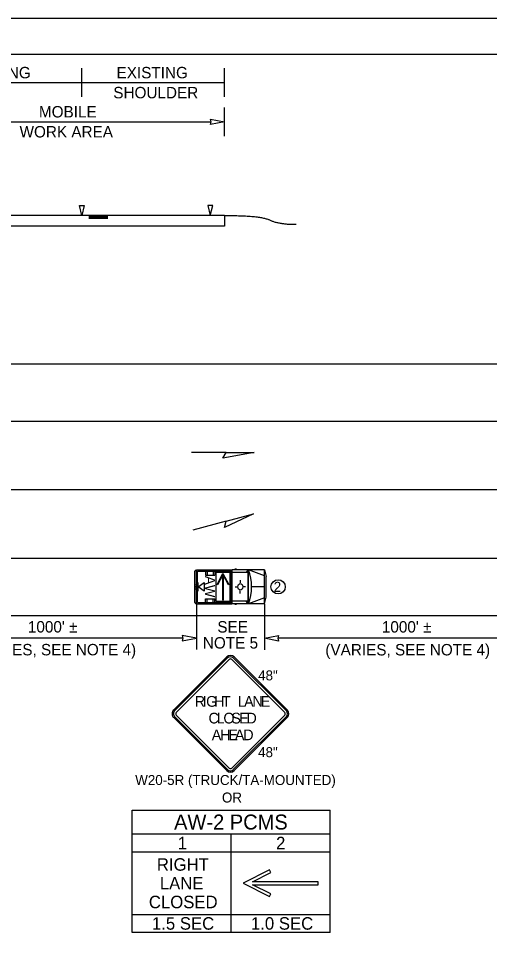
# Model space of a CAD drawing. Extents: x 0 to 17, y 0 to 11.
# Drawn here: x 8.41 to 11.71, y 4.59 to 11 of the extents above; entities that cross this region are included whole.
import ezdxf

# ---------------------------------------------------------------- set-up
doc = ezdxf.new("R2010")
doc.units = 0
for name, color, linetype in [('RD_ED_ShoulderPavedEdge', 7, 'Continuous'), ('RD_MK_LineEdgeWhite', 7, 'Continuous'), ('RD_MK_LineEdgeYellow', 7, 'Continuous'), ('RD_MK_LineLane', 7, 'Continuous'), ('SH_GI_PlotLimits', 7, 'Continuous'), ('SH_GI_SheetBorder3', 7, 'Continuous'), ('SH_TI_WZSectionCut', 7, 'Continuous'), ('TR_SN_ConstructionSigns', 7, 'Continuous'), ('TR_WZ_PortableChangeMessageSign', 7, 'Continuous'), ('TR_WZ_PortableSignMountBlk-Org', 7, 'Continuous'), ('TR_WZ_ProtectiveVehicle', 7, 'Continuous'), ('TR_WZ_TransportableAttenuator', 7, 'Continuous'), ('TR_WZ_WorkZoneDetails', 7, 'Continuous'), ('TR_WZ_WorkZoneTextCurrent', 7, 'Continuous')]:
    doc.layers.add(name, color=color, linetype=linetype)

msp = doc.modelspace()

# ---------------------------------------------------------------- linework, layer by layer
at = {"layer": 'RD_ED_ShoulderPavedEdge'}
for p, q in [((1.8283, 8.5807), (16.62, 8.5807)), ((1.8283, 6.8207), (16.62, 6.8207))]:
    msp.add_line(p, q, dxfattribs=at)
at = {"layer": 'RD_MK_LineEdgeWhite'}
msp.add_line((1.8283, 7.2207), (16.62, 7.2207), dxfattribs=at)
at = {"layer": 'RD_MK_LineEdgeYellow'}
msp.add_line((1.8283, 8.1807), (16.62, 8.1807), dxfattribs=at)
at = {"layer": 'RD_MK_LineLane'}
msp.add_line((16.62, 7.7007), (1.8283, 7.7007), dxfattribs=at)
at = {"layer": 'SH_GI_PlotLimits'}
msp.add_lwpolyline([(0, 11), (17, 11), (17, 0), (0, 0)], close=True, dxfattribs=at)
at = {"layer": 'SH_GI_SheetBorder3'}
msp.add_line((1, 10.75), (16.75, 10.75), dxfattribs=at)
at = {"layer": 'SH_TI_WZSectionCut'}
for p, q in [((8.8546, 10.45), (8.8546, 10.65)), ((9.8546, 10.45), (9.8546, 10.65)), ((7.6546, 10.55), (8.8546, 10.55)), ((8.8546, 10.55), (9.8546, 10.55)), ((9.8546, 10.176), (9.8546, 10.376)), ((7.7484, 10.276), (9.7609, 10.276)), ((9.8546, 9.6199), (5.4546, 9.6199)), ((9.0376, 9.6143), (8.9046, 9.6143)), ((9.0376, 9.6087), (8.9046, 9.6087)), ((9.0376, 9.603), (8.9046, 9.603)), ((9.0376, 9.5978), (8.9046, 9.5978)), ((9.8546, 9.6199), (9.8546, 9.5449)), ((9.8546, 9.5449), (5.4546, 9.5449))]:
    msp.add_line(p, q, dxfattribs=at)
for points in [[(9.8546, 10.276), (9.7564, 10.2567), (9.7609, 10.276), (9.7564, 10.2953)], [(8.838, 9.6897), (8.8713, 9.6897), (8.8547, 9.6199)]]:
    msp.add_lwpolyline(points, close=True, dxfattribs=at)
msp.add_lwpolyline([(9.7713, 9.6897), (9.7379, 9.6897), (9.7546, 9.6199), (9.7713, 9.6897)], dxfattribs=at)
msp.add_open_spline([(9.8546, 9.6199), (10.1058, 9.6201), (10.2313, 9.558), (10.3568, 9.5581)], degree=2, dxfattribs=at)
at = {"layer": 'TR_SN_ConstructionSigns'}
for p, q in [((9.8694, 6.5301), (9.4982, 6.1588)), ((9.876, 6.5234), (9.5048, 6.1522)), ((9.5158, 6.1411), (9.8871, 6.5124)), ((9.9048, 6.5124), (10.276, 6.1411)), ((10.2871, 6.1522), (9.9158, 6.5234)), ((10.2937, 6.1588), (9.9224, 6.5301)), ((9.4982, 6.1058), (9.8694, 5.7345)), ((9.5048, 6.1124), (9.876, 5.7412)), ((9.8871, 5.7522), (9.5158, 6.1235)), ((10.276, 6.1235), (9.9048, 5.7522)), ((9.9158, 5.7412), (10.2871, 6.1124)), ((9.9224, 5.7345), (10.2937, 6.1058))]:
    msp.add_line(p, q, dxfattribs=at)
for centre, radius, start, end in [((9.8959, 6.5036), 0.0375, 45, 135), ((9.8959, 6.5036), 0.0281, 45, 135), ((9.8959, 6.5036), 0.0125, 45, 135), ((9.5247, 6.1323), 0.0375, 135, 225.00001), ((10.2672, 6.1323), 0.0375, 315.00001, 45.00001), ((9.5247, 6.1323), 0.0281, 135, 225.00001), ((9.5247, 6.1323), 0.0125, 135, 225.00001), ((10.2672, 6.1323), 0.0125, 315.00002, 45), ((10.2672, 6.1323), 0.0281, 315.00002, 45), ((9.8959, 5.7611), 0.0375, 225.00001, 315.00001), ((9.8959, 5.7611), 0.0281, 225.00001, 315.00002), ((9.8959, 5.7611), 0.0125, 225.00001, 315.00002)]:
    msp.add_arc(centre, radius, start, end, dxfattribs=at)
at = {"layer": 'TR_WZ_PortableChangeMessageSign'}
for p, q in [((9.2079, 5.4586), (10.5939, 5.4586)), ((9.2079, 4.6018), (9.2079, 5.4586)), ((10.5939, 4.6018), (10.5939, 5.4586)), ((10.5939, 5.2906), (9.2079, 5.2906)), ((9.9009, 4.6018), (9.9009, 5.2906)), ((9.9009, 5.1646), (9.2079, 5.1646)), ((10.5939, 5.1646), (9.9009, 5.1646)), ((10.1689, 5.0395), (9.9849, 4.9462)), ((10.5099, 4.9567), (10.0501, 4.9567)), ((10.5099, 4.9357), (10.5099, 4.9567)), ((10.0501, 4.9357), (10.5099, 4.9357)), ((9.2079, 4.7278), (9.9009, 4.7278)), ((9.9009, 4.7278), (10.5939, 4.7278)), ((10.5939, 4.6018), (9.2079, 4.6018))]:
    msp.add_line(p, q, dxfattribs=at)
for points in [[(10.0501, 4.9567), (10.1783, 5.0208), (10.1736, 5.0302), (10.1689, 5.0395)], [(9.9849, 4.9462), (10.1689, 4.8528), (10.1736, 4.8622), (10.1783, 4.8715), (10.0501, 4.9357)]]:
    msp.add_lwpolyline(points, dxfattribs=at)
at = {"layer": 'TR_WZ_PortableSignMountBlk-Org'}
msp.add_line((9.6696, 6.9907), (9.6696, 7.0507), dxfattribs=at)
msp.add_lwpolyline([(9.6696, 7.0207), (9.7127, 7.0507), (9.7127, 6.9907)], close=True, dxfattribs=at)
at = {"layer": 'TR_WZ_ProtectiveVehicle'}
for p, q in [((9.6462, 6.912), (9.6462, 7.1295)), ((9.6515, 7.1368), (9.6569, 7.1368)), ((9.6569, 6.9047), (9.6569, 7.1368)), ((9.6577, 7.1407), (9.9046, 7.1407)), ((9.6577, 6.9007), (9.6577, 7.1407)), ((9.6647, 6.9103), (9.6647, 7.1312)), ((9.6647, 7.1312), (9.8976, 7.1312)), ((9.7204, 7.1312), (9.7204, 7.1035)), ((9.7335, 7.1312), (9.7335, 7.1035)), ((9.7743, 7.1312), (9.7743, 7.1035)), ((9.7863, 7.1312), (9.7863, 7.1035)), ((9.8976, 6.9103), (9.8976, 7.1312)), ((9.9046, 6.9007), (9.9046, 7.1407)), ((9.9079, 6.9007), (9.9079, 7.1407)), ((10.1346, 7.1407), (9.9079, 7.1407)), ((10.0192, 7.1221), (9.9079, 7.1221)), ((9.9388, 7.1441), (9.9252, 7.1441)), ((10.0072, 7.1221), (10.0192, 7.1407)), ((10.0192, 6.9007), (10.0192, 7.1407)), ((10.0212, 6.9007), (10.0212, 7.1407)), ((10.1346, 7.0968), (10.0212, 7.1407)), ((10.1346, 6.9007), (10.1346, 7.1407)), ((10.1346, 7.1407), (10.1457, 7.0923)), ((9.7204, 7.1035), (9.7863, 7.1035)), ((9.9639, 7.0669), (9.9642, 7.0488)), ((10.1457, 6.9492), (10.1457, 7.0923)), ((9.6462, 7.0376), (9.6569, 7.0331)), ((9.6462, 7.0038), (9.6569, 7.0083)), ((9.6491, 7.0207), (9.654, 7.0207)), ((9.6515, 7.0173), (9.6515, 7.0241)), ((9.9277, 7.0216), (9.9456, 7.0212)), ((9.9479, 7.0211), (9.9479, 7.0211)), ((9.9648, 6.9732), (9.9648, 6.9925)), ((10.0009, 7.0206), (9.9858, 7.0206)), ((10.1346, 7.0207), (10.0435, 7.0207)), ((9.7204, 6.9379), (9.7863, 6.9379)), ((9.7204, 6.9103), (9.7204, 6.9379)), ((9.7335, 6.9103), (9.7335, 6.9379)), ((9.7743, 6.9103), (9.7743, 6.9379)), ((9.7863, 6.9103), (9.7863, 6.9379)), ((10.1346, 6.9447), (10.0212, 6.9007)), ((10.1346, 6.9007), (10.1457, 6.9492)), ((9.6515, 6.9047), (9.6569, 6.9047)), ((9.6577, 6.9007), (9.9046, 6.9007)), ((9.6647, 6.9103), (9.8976, 6.9103)), ((10.0192, 6.9193), (9.9079, 6.9193)), ((10.1346, 6.9007), (9.9079, 6.9007)), ((9.9388, 6.8973), (9.9252, 6.8973)), ((10.0192, 6.9007), (10.0047, 6.9193))]:
    msp.add_line(p, q, dxfattribs=at)
for centre, major_axis, start_param, end_param in [((9.6515, 7.1295), (0, 0.00732), 0, 1.570796), ((9.8592, 7.0208), (0, 0.2518), 4.215667, 5.208926), ((9.6515, 6.912), (0, -0.00732), 4.712389, 6.283185)]:
    msp.add_ellipse(centre, major_axis=major_axis, ratio=0.73155, start_param=start_param, end_param=end_param, dxfattribs=at)
for centre, major_axis in [((9.6515, 7.0207), (0, -0.00338)), ((9.9648, 7.0207), (0, -0.0231))]:
    msp.add_ellipse(centre, major_axis=major_axis, ratio=0.73155, dxfattribs=at)
at = {"layer": 'TR_WZ_TransportableAttenuator'}
for points in [[(9.795, 7.1225), (9.891, 7.1225), (9.891, 6.9189), (9.795, 6.9189)], [(9.8016, 7.0368), (9.843, 7.1143), (9.8414, 7.1041), (9.8043, 7.0346)], [(9.843, 7.1143), (9.8446, 7.1041), (9.8414, 7.1041)], [(9.8414, 6.9271), (9.8414, 7.1041), (9.8446, 7.1041), (9.8446, 6.9271)], [(9.843, 7.1143), (9.8843, 7.0368), (9.8816, 7.0346), (9.8446, 7.1041)]]:
    msp.add_lwpolyline(points, close=True, dxfattribs=at)
at = {"layer": 'TR_WZ_WorkZoneDetails'}
for p, q in [((9.865, 7.96), (9.6239, 7.96)), ((9.8664, 7.48), (9.6335, 7.4176)), ((9.6569, 6.9007), (9.6569, 6.5811)), ((10.1346, 6.9007), (10.1346, 6.5807)), ((9.5632, 6.6611), (7.7506, 6.6611)), ((12.0408, 6.6607), (10.2283, 6.6607))]:
    msp.add_line(p, q, dxfattribs=at)
for points in [[(10.0616, 7.96), (9.8428, 7.9214), (9.865, 7.96)], [(10.0562, 7.5309), (9.8549, 7.437), (9.8664, 7.48)], [(9.6569, 6.6611), (9.5586, 6.6803), (9.5632, 6.6611), (9.5586, 6.6418)], [(10.1346, 6.6607), (10.2328, 6.68), (10.2283, 6.6607), (10.2328, 6.6415)]]:
    msp.add_lwpolyline(points, close=True, dxfattribs=at)
msp.add_circle((10.2294, 7.0207), 0.05, dxfattribs=at)

# ---------------------------------------------------------------- texts
at = {"layer": 'SH_TI_WZSectionCut'}
for s, p in [('EXISTING', (7.9986, 10.58)), ('EXISTING', (9.0986, 10.58)), ('SHOULDER', (9.0757, 10.44))]:
    msp.add_text(s, height=0.08, rotation=360, dxfattribs=at).set_placement(p)
for s, p in [('MOBILE', (8.5551, 10.306)), ('WORK AREA', (8.4196, 10.166))]:
    msp.add_text(s, height=0.08, dxfattribs=at).set_placement(p)
at = {"layer": 'TR_SN_ConstructionSigns'}
for s, height, p in [('48"', 0.07, (10.0895, 6.366)), ('R', 0.075, (9.6454, 6.1815)), ('I', 0.075, (9.7002, 6.1815)), ('G', 0.075, (9.7257, 6.1815)), ('H', 0.075, (9.7827, 6.1815)), ('T', 0.075, (9.8352, 6.1815)), ('L', 0.075, (9.9484, 6.1815)), ('A', 0.075, (9.9912, 6.1815)), ('N', 0.075, (10.0497, 6.1815)), ('E', 0.075, (10.1082, 6.1815)), ('C', 0.075, (9.7422, 6.0643)), ('L', 0.075, (9.7992, 6.0643)), ('O', 0.075, (9.8464, 6.0643)), ('S', 0.075, (9.9019, 6.0643)), ('E', 0.075, (9.9567, 6.0643)), ('D', 0.075, (10.0077, 6.0643)), ('A', 0.075, (9.7647, 5.9471)), ('H', 0.075, (9.8232, 5.9471)), ('E', 0.075, (9.8817, 5.9471)), ('A', 0.075, (9.9267, 5.9471)), ('D', 0.075, (9.9852, 5.9471)), ('48"', 0.07, (10.0895, 5.8286)), ('W20-5R (TRUCK/TA-MOUNTED)', 0.07, (9.229, 5.6336)), ('OR', 0.07, (9.8361, 5.5111))]:
    msp.add_text(s, height=height, dxfattribs=at).set_placement(p)
at = {"layer": 'TR_WZ_PortableChangeMessageSign'}
for s, height, p in [('AW-2 PCMS', 0.105, (9.5011, 5.3221)), ('1', 0.0875, (9.527, 5.1838)), ('2', 0.0875, (10.215, 5.1838)), ('RIGHT', 0.0875, (9.3805, 5.0337)), ('LANE', 0.0875, (9.4012, 4.9024)), ('CLOSED', 0.0875, (9.3247, 4.7712)), ('1.5 SEC', 0.0875, (9.3462, 4.621)), ('1.0 SEC', 0.0875, (10.0392, 4.621))]:
    msp.add_text(s, height=height, rotation=360, dxfattribs=at).set_placement(p)
at = {"layer": 'TR_WZ_ProtectiveVehicle'}
msp.add_text('AW', height=0.07, rotation=270, dxfattribs=at).set_placement((9.7183, 7.0974))
at = {"layer": 'TR_WZ_WorkZoneDetails'}
msp.add_text('2', height=0.07, dxfattribs=at).set_placement((10.1986, 6.9857))
at = {"layer": 'TR_WZ_WorkZoneTextCurrent'}
for s, p in [("1000' ±", (8.4778, 6.7011)), ('SEE', (9.8039, 6.7007)), ("1000' ±", (10.9555, 6.7007)), ('(VARIES, SEE NOTE 4)', (8.0822, 6.5411)), ('NOTE 5', (9.7026, 6.5887)), ('(VARIES, SEE NOTE 4)', (10.5599, 6.5407))]:
    msp.add_text(s, height=0.08, dxfattribs=at).set_placement(p)

doc.saveas('drawing.dxf')
